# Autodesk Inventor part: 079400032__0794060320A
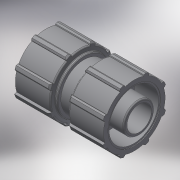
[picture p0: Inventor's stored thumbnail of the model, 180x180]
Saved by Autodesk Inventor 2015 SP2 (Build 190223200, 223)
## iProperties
Created: 2017-04
Part Number: 079400032__0794060320A
Material: Generic
Description: PLASSON MODULAR ADAPTOR 32
Document SubType Name: Modeling
Designer: KIM
Mass: 135.166 g
Surface Area: 436.294 cm^2
Volume: 135.166 cm^3
Density: 1 g/cm^3
Appearance: Default
Author: KIM
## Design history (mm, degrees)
derived "07940.ipt"
feature "Solid1::07940.ipt"
tag "TaggingFeature1"
body "Solid1"
other parameters: "d7" = 64, "d8" = 51.2, "d9" = 32, "d15" = 48, "d17" = 37.2, "d43" = 100 deg, "d46" = 59.52, "d47" = 35 deg, "d48" = 17.5 deg, "d50" = 0, "d52" = 360 deg, "d54" = 1.28, "d57" = 1.28, "d68" = 33.48, "d69" = 0.5, "d70" = 3.348, "d71" = 5, "d72" = 25.6, "d73" = 46.5, "d74" = 41.85, "d75" = 44.8, "d76" = 0.64, "d77" = 1.28, "d79" = 360 deg, "d81" = 1.28, "d82" = 18.6, "d_" = 32, "E_" = 64, "H_" = 93
